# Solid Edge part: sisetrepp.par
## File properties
Author: Mac
Template: Normal.par
Last saved by: Mac
Revision: 1
Application: Solid Edge
Density: 600,000 kg/m^3
Accuracy: 0,990
Material: Wood, Mahogany
Face Style: Tan
Fill Style: Cork
Virtual Style: Mahogany
Coef. of Thermal Exp: 0.0
Thermal Conductivity: 0.0
Specific Heat: 0.0
Modulus of Elasticity: 0.0
Poission's Ratio: 0.0
Yield Stress: 0.0
Ultimate Stress: 0.0
Elongation: 0.0
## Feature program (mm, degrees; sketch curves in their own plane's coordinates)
swept protrusion "unnamed SweptProtrusion 1"
sketch for "unnamed Cutout 1" #1 plane through (0, 0, 0) normal (1, 0, 0) x-axis (0, 1, 0)
  line (7.1, 19.97) -> (-7.1, 19.97)
  line (-7.1, 19.97) -> (-7.1, 15.97)
  line (-7.1, 15.97) -> (7.1, 15.97)
  line (7.1, 19.97) -> (7.1, 15.97)
sketch for "unnamed Cutout 1" #2 plane through (0, 0, 0) normal (1, 0, 0) x-axis (0, 1, 0)
  line (-7.1, 0) -> (7.1, 0)
  line (7.1, 3.37) -> (7.1, 0)
  line (-7.1, 3.37) -> (7.1, 3.37)
  line (-7.1, 3.37) -> (-7.1, 0)
sketch for "unnamed Cutout 1" #3 plane through (0, 0, 0) normal (1, 0, 0) x-axis (0, 1, 0)
  line (-7.1, 11.97) -> (7.1, 11.97)
  line (7.1, 15.37) -> (7.1, 11.97)
  line (-7.1, 15.37) -> (7.1, 15.37)
  line (-7.1, 15.37) -> (-7.1, 11.97)
sketch for "unnamed Cutout 1" #4 plane through (0, 0, 0) normal (1, 0, 0) x-axis (0, 1, 0)
  line (7.1, 7.97) -> (-7.1, 7.97)
  line (-7.1, 11.37) -> (-7.1, 7.97)
  line (-7.1, 11.37) -> (7.1, 11.37)
  line (7.1, 11.37) -> (7.1, 7.97)
sketch for "unnamed Cutout 1" #5 plane through (0, 0, 0) normal (1, 0, 0) x-axis (0, 1, 0)
  line (-7.1, 7.37) -> (-7.1, 3.97)
  line (-7.1, 3.97) -> (7.1, 3.97)
  line (7.1, 7.37) -> (7.1, 3.97)
  line (7.1, 7.37) -> (-7.1, 7.37)
extrude "unnamed Cutout 1" cut through along +normal
sketch for "unnamed Cutout 2" plane through (0, 0, 0) normal (0, -1, 0) x-axis (1, 0, 0)
  line (0.8012, 17.629) -> (0.8012, 20.1299)
  line (-0.5069, 20.1299) -> (0.8012, 20.1299)
  line (-0.5069, 17.629) -> (-0.5069, 20.1299)
  line (0.8012, 17.629) -> (-0.5069, 17.629)
extrude "unnamed Cutout 2" cut finite 42.9783 symmetric
fillet "Round_1" radius 0.1
fillet "Round_2" radius 0.5
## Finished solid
Body 1: solid body, 51 faces, 140 edges, 88 vertices.
  Faces by surface: plane 29, cylinder 10, blend 8, spline 4
  Edges by curve: line 88, intersection 32, circle 20
Bounding box of the edges (mm; curved faces can reach further): 10.199 x 15.000 x 19.970, from (0.8012, -7.5, 0) to (11, 7.5, 19.97).
Cylindrical faces by radius (mm): R0.1 x8, R0.5 x2
Planar faces by outward normal: +y 6, +z 6, -x 2, -y 6, -z 6, oblique 3
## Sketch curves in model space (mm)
line (8, 7.5, 0) -> (11, 7.5, 0)
line (11, 7.1, 0) -> (11, 7.5, 0)
spline (11, 7.1, 0) -> (12, 0, 0) -> (11, -7.1, 0)
line (11, -7.1, 0) -> (11, -7.5, 0)
line (8, -7.5, 0) -> (11, -7.5, 0)
line (8, -7.5, 0) -> (8, 7.5, 0)
line (0, 0, 19.97) -> (8, 0, 0)
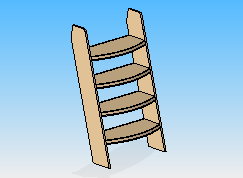
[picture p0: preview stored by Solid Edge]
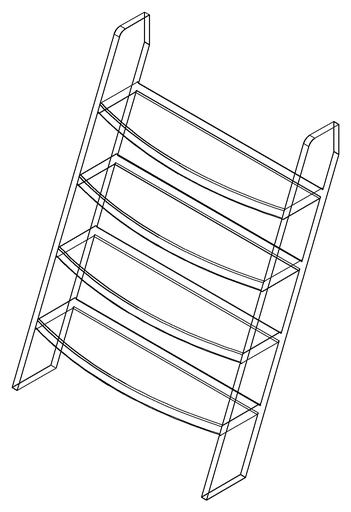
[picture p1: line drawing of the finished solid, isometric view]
